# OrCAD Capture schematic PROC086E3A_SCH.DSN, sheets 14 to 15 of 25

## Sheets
14 16. VOUT MUX SELECTION: size C; title: VIN/VOUT MUX SELECTION
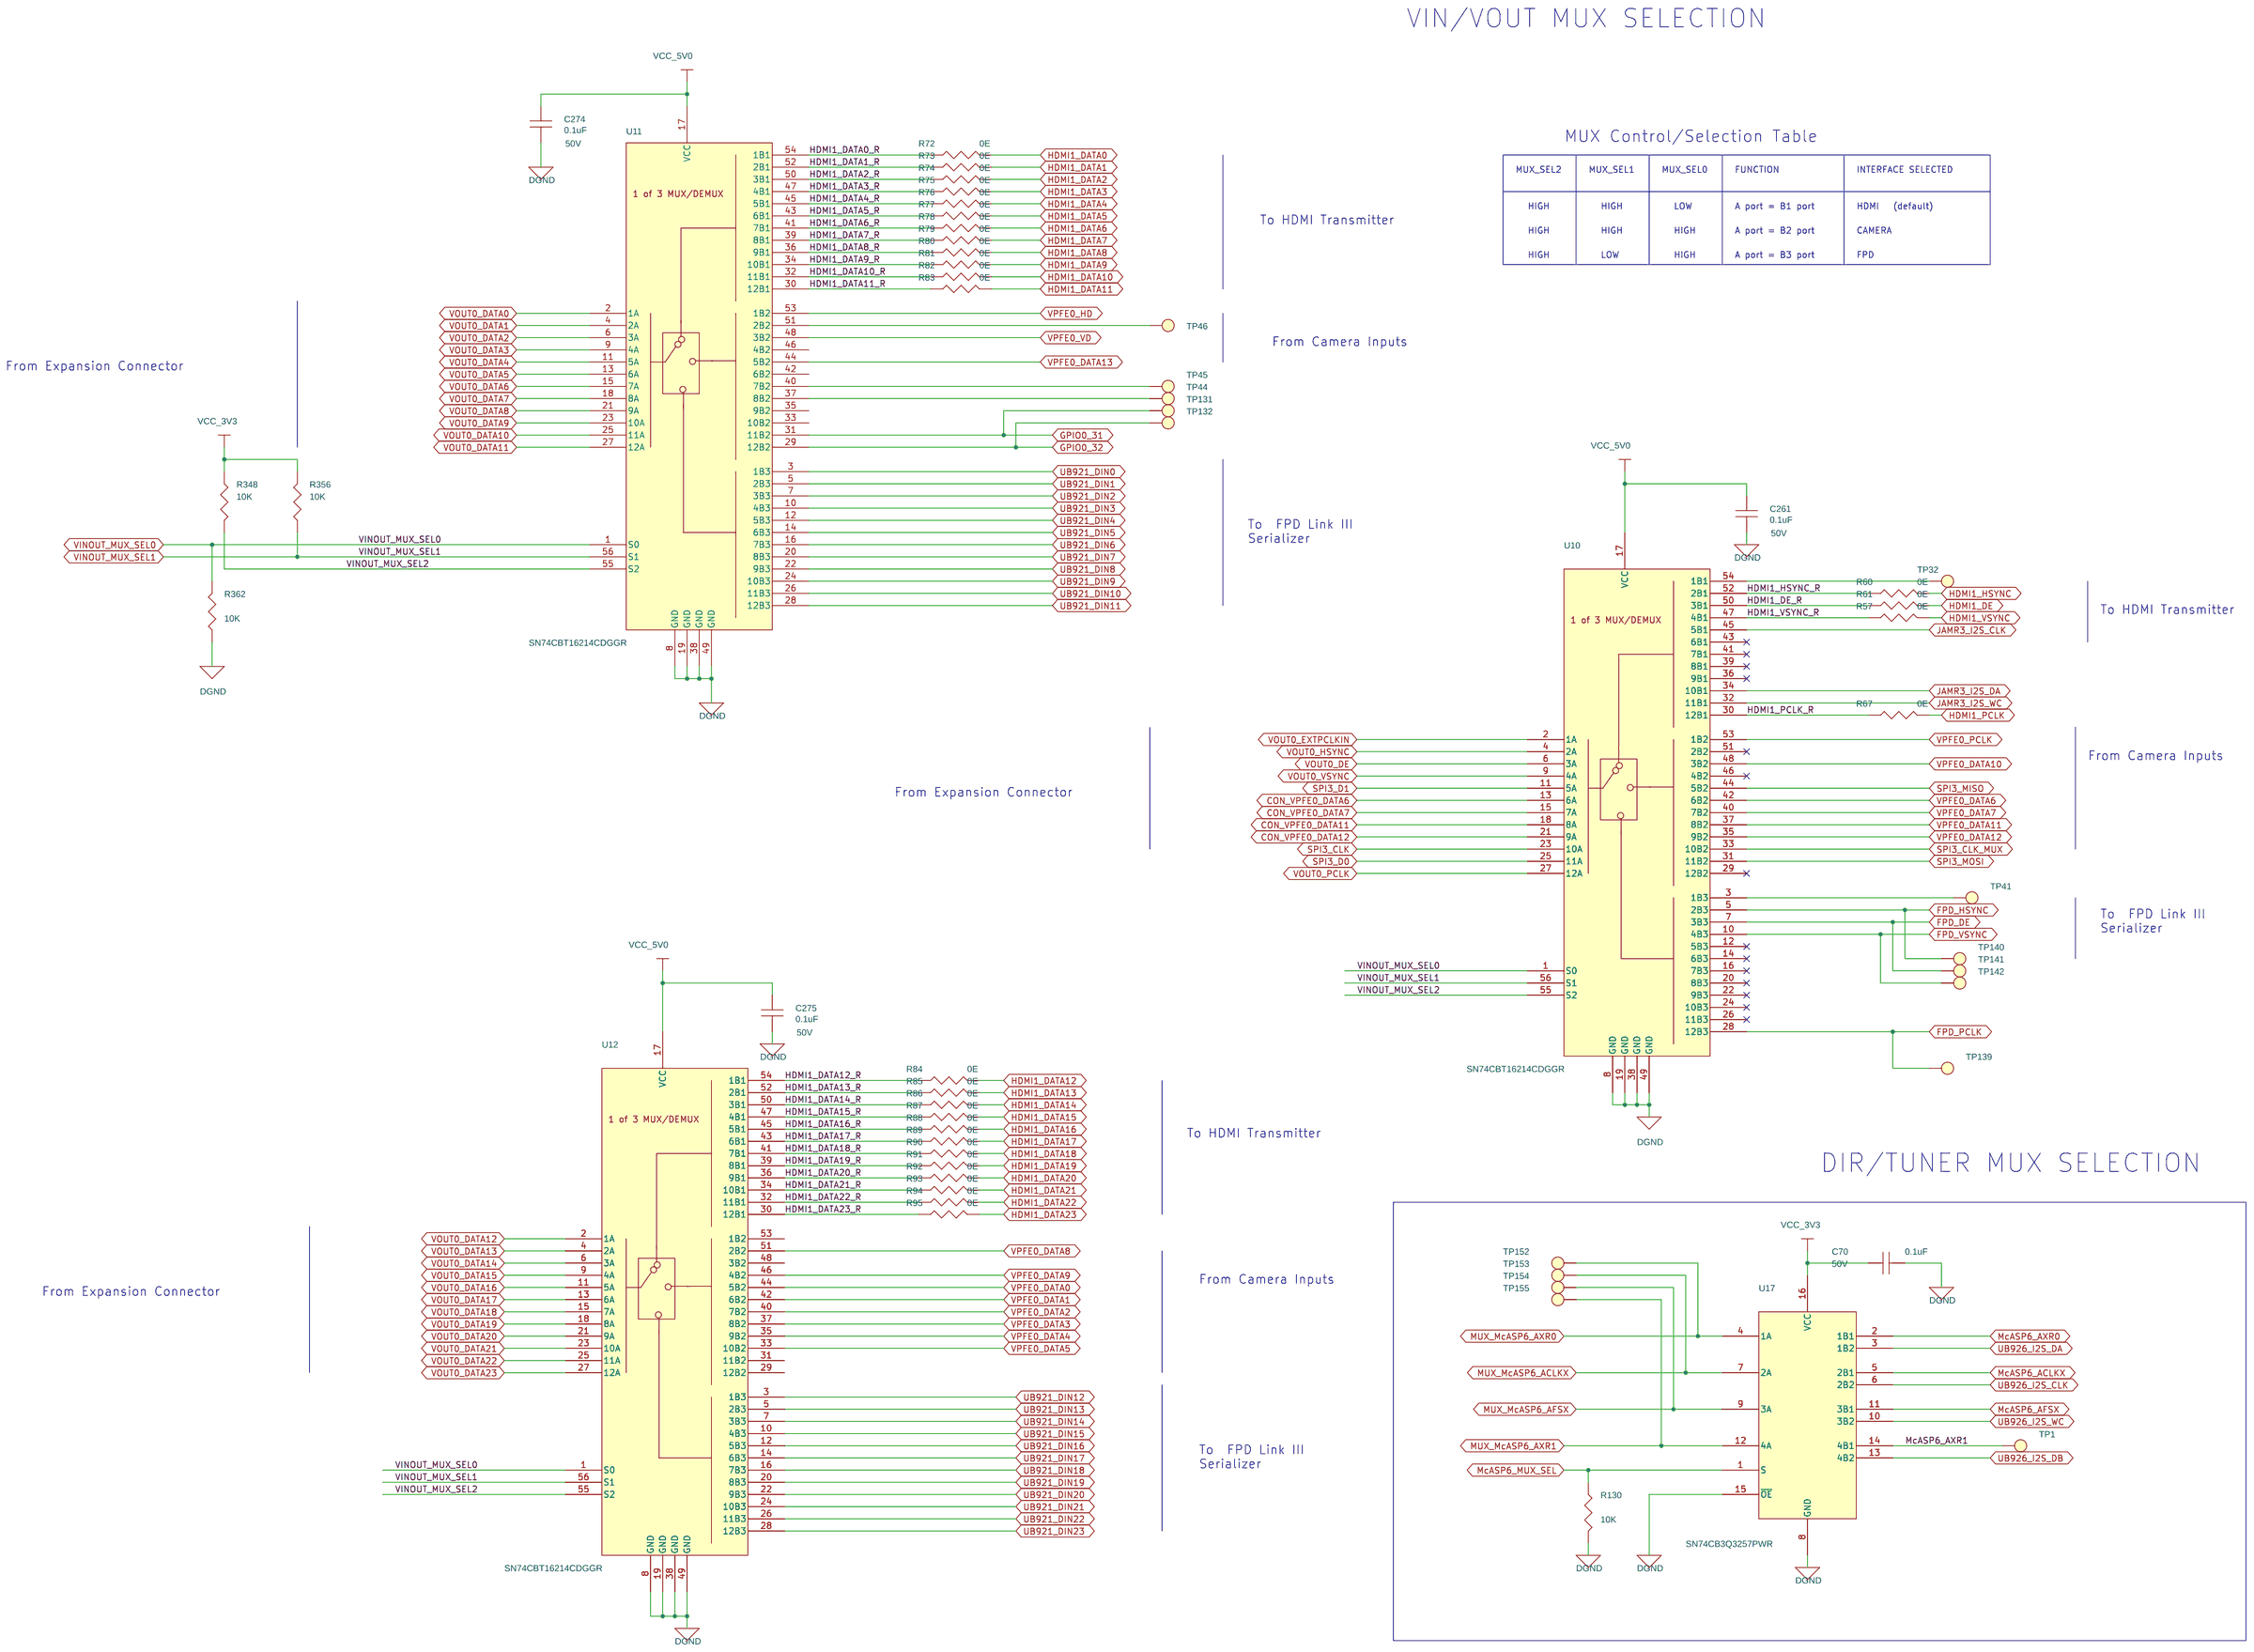
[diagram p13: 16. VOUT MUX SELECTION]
15 17. HDMI BRIDGE: size C; title: HDMI BRIDGE
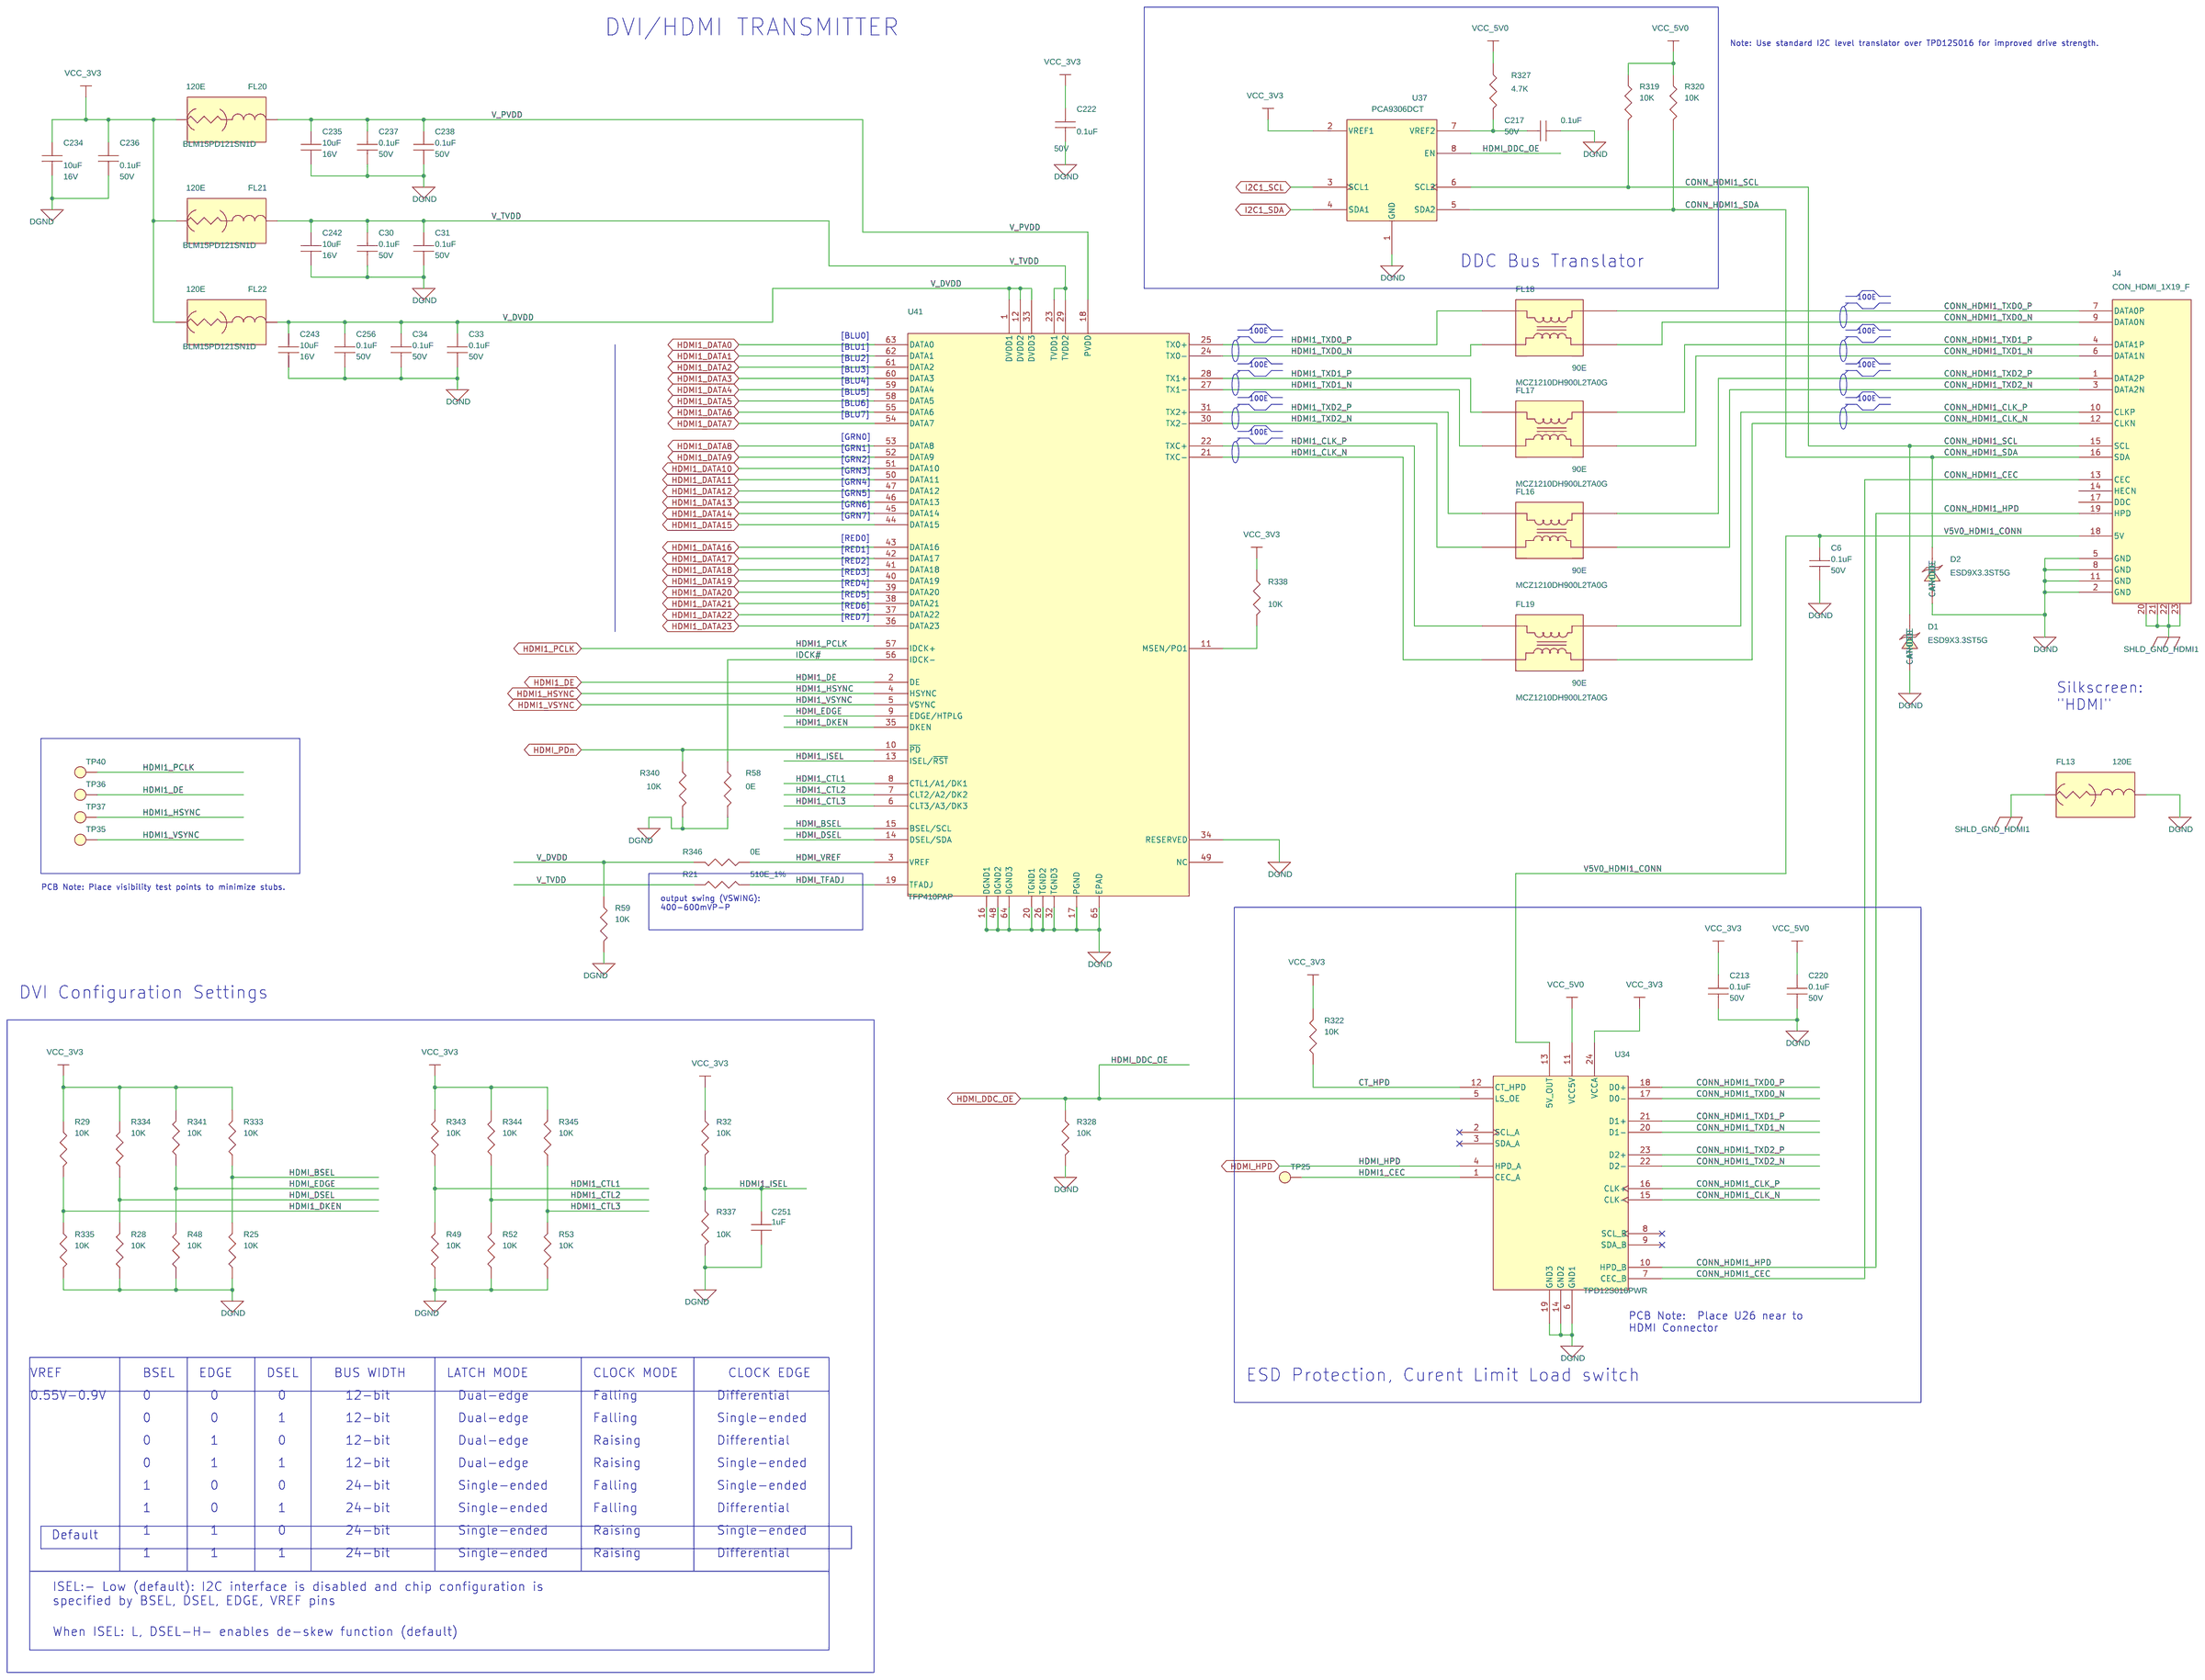
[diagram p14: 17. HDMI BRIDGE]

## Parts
sheet 16. VOUT MUX SELECTION
C70  0.1uF  [CAP0402_0-75]
C261  0.1uF  [CAP0402_0-75]
C274  0.1uF  [CAP0402_0-75]
C275  0.1uF  [CAP0402_0-75]
R57  0E  [RES0402_0-5]
R60  0E  [RES0402_0-5]
R61  0E  [RES0402_0-5]
R67  0E  [RES0402_0-5]
R72  0E  [RES0402_0-5]
R73  0E  [RES0402_0-5]
R74  0E  [RES0402_0-5]
R75  0E  [RES0402_0-5]
R76  0E  [RES0402_0-5]
R77  0E  [RES0402_0-5]
R78  0E  [RES0402_0-5]
R79  0E  [RES0402_0-5]
R80  0E  [RES0402_0-5]
R81  0E  [RES0402_0-5]
R82  0E  [RES0402_0-5]
R83  0E  [RES0402_0-5]
R84  0E  [RES0402_0-5]
R85  0E  [RES0402_0-5]
R86  0E  [RES0402_0-5]
R87  0E  [RES0402_0-5]
R88  0E  [RES0402_0-5]
R89  0E  [RES0402_0-5]
R90  0E  [RES0402_0-5]
R91  0E  [RES0402_0-5]
R92  0E  [RES0402_0-5]
R93  0E  [RES0402_0-5]
R94  0E  [RES0402_0-5]
R95  0E  [RES0402_0-5]
R130  10K  [RES0402_0-5]
R348  10K  [RES0402_0-5]
R356  10K  [RES0402_0-5]
R362  10K  [RES0402_0-5]
TP1  TP40_SMD  [TP40_SMD]
TP32  TP40_SMD  [TP40_SMD]
TP41  TP40_SMD  [TP40_SMD]
TP44  TP40_SMD  [TP40_SMD]
TP45  TP40_SMD  [TP40_SMD]
TP46  TP40_SMD  [TP40_SMD]
TP131  TP20_SMD  [TP20_SMD]
TP132  TP20_SMD  [TP20_SMD]
TP139  TP20_SMD  [TP20_SMD]
TP140  TP20_SMD  [TP20_SMD]
TP141  TP20_SMD  [TP20_SMD]
TP142  TP20_SMD  [TP20_SMD]
TP152  TP20_SMD  [TP20_SMD]
TP153  TP20_SMD  [TP20_SMD]
TP154  TP20_SMD  [TP20_SMD]
TP155  TP20_SMD  [TP20_SMD]
U10  SN74CBT16214CDGGR  [TSSOP56_19-68_560X240_1-2]
U11  SN74CBT16214CDGGR  [TSSOP56_19-68_560X240_1-2]
U12  SN74CBT16214CDGGR  [TSSOP56_19-68_560X240_1-2]
U17  SN74CB3Q3257PWR  [TSSOP16_25-59_205X180]
sheet 17. HDMI BRIDGE
C6  0.1uF  [CAP0402_0-75]
C30  0.1uF  [CAP0402_0-75]
C31  0.1uF  [CAP0402_0-75]
C33  0.1uF  [CAP0402_0-75]
C34  0.1uF  [CAP0402_0-75]
C213  0.1uF  [CAP0402_0-75]
C217  0.1uF  [CAP0402_0-75]
C220  0.1uF  [CAP0402_0-75]
C222  0.1uF  [CAP0402_0-75]
C234  10uF  [CAP0603_1]
C235  10uF  [CAP0603_1]
C236  0.1uF  [CAP0402_0-75]
C237  0.1uF  [CAP0402_0-75]
C238  0.1uF  [CAP0402_0-75]
C242  10uF  [CAP0603_1]
C243  10uF  [CAP0603_1]
C251  1uF  [CAP0402_0-5]
C256  0.1uF  [CAP0402_0-75]
D1  ESD9X3.3ST5G  [DIO_SOD923_0-5]
D2  ESD9X3.3ST5G  [DIO_SOD923_0-5]
FL13  120E  [EMIFIL_BLM15A_0402_0-6]
FL16  90E  [FILT4_MCZ1210DH_60X50_SMD_0-6]
FL17  90E  [FILT4_MCZ1210DH_60X50_SMD_0-6]
FL18  90E  [FILT4_MCZ1210DH_60X50_SMD_0-6]
FL19  90E  [FILT4_MCZ1210DH_60X50_SMD_0-6]
FL20  120E  [EMIFIL_BLM15A_0402_0-6]
FL21  120E  [EMIFIL_BLM15A_0402_0-6]
FL22  120E  [EMIFIL_BLM15A_0402_0-6]
J4  CON_HDMI_1X19_F  [CON_19X1_10029449-001RLF_S_R_S_6-3]
R21  510E_1%  [RES0402_0-5]
R25  10K  [RES0402_0-5]
R28  10K  [RES0402_0-5]
R29  10K  [RES0402_0-5]
R32  10K  [RES0402_0-5]
R48  10K  [RES0402_0-5]
R49  10K  [RES0402_0-5]
R52  10K  [RES0402_0-5]
R53  10K  [RES0402_0-5]
R58  0E  [RES0402_0-5]
R59  10K  [RES0402_0-5]
R319  10K  [RES0402_0-5]
R320  10K  [RES0402_0-5]
R322  10K  [RES0402_0-5]
R327  4.7K  [RES0402_0-5]
R328  10K  [RES0402_0-5]
R333  10K  [RES0402_0-5]
R334  10K  [RES0402_0-5]
R335  10K  [RES0402_0-5]
R337  10K  [RES0402_0-5]
R338  10K  [RES0402_0-5]
R340  10K  [RES0402_0-5]
R341  10K  [RES0402_0-5]
R343  10K  [RES0402_0-5]
R344  10K  [RES0402_0-5]
R345  10K  [RES0402_0-5]
R346  0E  [RES0402_0-5]
TP25  TP40_SMD  [TP40_SMD]
TP35  TP20_SMD  [TP20_SMD]
TP36  TP20_SMD  [TP20_SMD]
TP37  TP20_SMD  [TP20_SMD]
TP40  TP20_SMD  [TP20_SMD]
U34  TPD12S016PWR  [TSSOP24_25-59_315X180_1-2]
U37  PCA9306DCT  [SSOP8_25-59_120X110]
U41  TFP410PAP  [HTQFP64_19-68_400X400_1-2]

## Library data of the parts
C6 C30 C31 C33 C34 C70 C213 C217 C220 C222 C236-C238 C256 C261 C274 C275 = CAP: CAP CERAMIC 0.1uF 50V 10% X7R 0402; Chkd/date: VASANTHA/281216; Crtd /date: CHAITHANYA/051011; Custom_Duty: 15%; Customs_HS_Code: 85322990; Distributor_name: DIGIKEY; Distributor_part_number: 445-173610-1-ND; Footprint Path: Y:\MIS_DATABASE\Library\ALTIUM_TOOL\PCB_FOOTPRINTS\Altium_Footprint_Lib.PcbLib; Height: 0.60MM; Library Path: Y:\MIS_DATABASE\Library\ALTIUM_TOOL\SCHEMATICS_PARTS\MS_DISCRETE_Library.schlib; Mfr_name: TDK CORPORATION; Mfr_part_number: C1005X7R1H104K050BE; Mistral Part No: 120011100014-R; Package: 0402; Part_type: CAPACITORS\CERAMIC; Project: VP-4000-BASE-BOARD; RoHS: RoHS; Temperature: -55°C+125°C; Tolerance: 10%; Voltage: 50V; Wattage: NA; Weight: 0.65mg; Datasheet: Y:\MIS_DATABASE\DATASHEETS\CAPACITORS\TDK_C-SER_FEB19.PDF
R57 R58 R60 R61 R67 R72-R95 R346 = RESISTOR: RES 0E 1/10W JUMPER 0402; Chkd/date: VASANTHA/061216; Crtd /date: NAVEED/201014; Custom_Duty: 15%; Customs_HS_Code: 85332119; Distributor_name: DIGIKEY; Distributor_part_number: P0.0JCT-ND; Footprint Path: Y:\MIS_DATABASE\Library\ALTIUM_TOOL\PCB_FOOTPRINTS\Altium_Footprint_Lib.PcbLib; Height: 0.40MM; IBISSP_MODLES: VALUE REPEATING 2 TIME; Library Path: Y:\MIS_DATABASE\Library\ALTIUM_TOOL\SCHEMATICS_PARTS\MS_DISCRETE_Library.schlib; Mfr_name: PANASONIC-ECG; Mfr_part_number: ERJ-2GE0R00X; Mistral Part No: 110018030052-R; Package: 0402; Part_type: RESISTORS\FIXED; Project: AEGIS POM; RoHS: RoHS; Temperature: -55°C+155°C; Tolerance: NA; Voltage: NA; Wattage: 1/10W; Weight: 0.8mg; Datasheet: Y:\MIS_DATABASE\DATASHEETS\RESISTORS\PAN-ERJSER_NOV17.PDF
R28 R29 R49 R52 R130 R319 R320 R322 R328 R333 R337 R338 R340 R341 R345 R348 R356 R362 = RESISTOR: RES 10K 1/16W 5% 0402; Chkd/date: VASANTHA/061216; Crtd /date: MAZHAR/230805; Custom_Duty: 15%; Customs_HS_Code: 85332119; Distributor_name: DIGIKEY; Distributor_part_number: 311-10KJRCT-ND; Footprint Path: Y:\MIS_DATABASE\Library\ALTIUM_TOOL\PCB_FOOTPRINTS\Altium_Footprint_Lib.PcbLib; Height: 0.40MM; Library Path: Y:\MIS_DATABASE\Library\ALTIUM_TOOL\SCHEMATICS_PARTS\MS_DISCRETE_Library.schlib; Mfr_name: YAGEO AMERICA; Mfr_part_number: RC0402JR-0710KL; Mistral Part No: 110011060021-R; Package: 0402; Part_type: RESISTORS\FIXED; Project: HSE; RoHS: RoHS; Temperature: -55°C+155°C; Tolerance: 5%; Voltage: NA; Wattage: 1/16W; Weight: 0.65mg; Datasheet: Y:\MIS_DATABASE\DATASHEETS\RESISTORS\RCXXXXL-SER_MAR18.PDF
TP1 TP25 TP32 TP41 TP44-TP46 = TESTPOINT: TESTPOINT CIR 40 SMD; Chkd/date: MAZHAR/190505; Crtd /date: MAZHAR/190505; Distributor_name: NA; Distributor_part_number: NA; Footprint Path: Y:\MIS_DATABASE\Library\ALTIUM_TOOL\PCB_FOOTPRINTS\Altium_Footprint_Lib.PcbLib; Height: NA; Library Path: Y:\MIS_DATABASE\Library\ALTIUM_TOOL\SCHEMATICS_PARTS\MS_DISCRETE_Library.schlib; MECHANICAL 3D STEP FILE: NA; Mfr_name: LOCAL; Mistral Part No: 130009030933; Package: SMD; Project: RAINIER-3; RoHS: NA; Temperature: NA; Tolerance: NA; Voltage: NA; Wattage: NA; Weight: NA; Datasheet: NA
TP35-TP37 TP40 TP131 TP132 TP139-TP142 TP152-TP155 = TESTPOINT: TESTPOINT CIR 20 SMD; Chkd/date: SHREESHAIL/171006; Crtd /date: MAZHAR/171006; Custom_Duty: NA; Customs_HS_Code: NA; Distributor_name: NA; Distributor_part_number: NA; Footprint Path: Y:\MIS_DATABASE\Library\ALTIUM_TOOL\PCB_FOOTPRINTS\Altium_Footprint_Lib.PcbLib; Height: NA; Library Path: Y:\MIS_DATABASE\Library\ALTIUM_TOOL\SCHEMATICS_PARTS\MS_DISCRETE_Library.schlib; MECHANICAL 3D STEP FILE: NA; Mfr_name: LOCAL; Mistral Part No: NA; Package: SMD; Project: BT MODULE_CSRBC04; RoHS: NA; Temperature: NA; Tolerance: NA; Voltage: NA; Wattage: NA; Weight: NA; Datasheet: NA
U10-U12 = SN74CBT16214CDGGR_TSSOP56_TI: IC 12BIT 1-OF-3 FET MULTIPLEXER/DEMULTIPLEXER TSSOP56; Chkd/date: VASANTHA/110216; Crtd /date: VASANTHA/110216; Custom_Duty: 15%; Customs_HS_Code: 85423100; Distributor_name: DIGIKEY; Distributor_part_number: 296-19173-1-ND; Footprint Path: Y:\MIS_DATABASE\Library\ALTIUM_TOOL\PCB_FOOTPRINTS\Altium_Footprint_Lib.PcbLib; Height: 1.20MM; Library Path: Y:\MIS_DATABASE\Library\ALTIUM_TOOL\SCHEMATICS_PARTS\MS_COMBINATIONAL_Library.schlib; Library Ref: SN74CBT16214CDGGR_TSSOP56; Mfr_name: TEXAS INSTRUMENTS; Mistral Part No: 141016020009-R; Package: TSSOP56; Part_type: ICS\DIGITAL\COMBINATIONAL; Project: DM368_EVM; RoHS: RoHS; Temperature: -40°C+85°C; Tolerance: NA; Voltage: NA; Wattage: NA; Weight: NA; Datasheet: Y:\MIS_DATABASE\DATASHEETS\ICS\DIGITAL\COMBINATIONAL\SN74CBT16214CD.PDF
U17 = SN74CB3Q3257PWR_TSSOP16: IC 4BIT 1-OF-2 FET MULTIPLEXER/DEMULTIPLEXER TSSOP16; Chkd/date: SUHAS/251010; Crtd /date: USMAN/060109; Custom_Duty: 15%; Customs_HS_Code: 85423100; Distributor_name: DIGIKEY; Distributor_part_number: 296-19138-1-ND; Height: 1.20MM; Mfr_name: TEXAS INSTRUMENTS; Mistral Part No: 141009030117-R; Package: TSSOP16; Part_type: ICS\DIGITAL\COMBINATIONAL; Project: OMAP_EVM; RoHS: Sb/ Br FREE; Temperature: -40°C+85°C; Datasheet: Y:\MIS_DATABASE\DATASHEETS\ICS\DIGITAL\COMBINATIONAL\SN74CB3Q3257.PDF
C234 C235 C242 C243 = CAP: CAP CERAMIC 10uF 16V 20% X6S 0603; Chkd/date: VASANTHA/170117; Crtd /date: VASANTHA/170117; Custom_Duty: 15%; Customs_HS_Code: 85322990; Distributor_name: DIGIKEY; Distributor_part_number: 490-7198-1-ND; Footprint Path: Y:\MIS_DATABASE\Library\ALTIUM_TOOL\PCB_FOOTPRINTS\Altium_Footprint_Lib.PcbLib; Height: 0.90MM; Library Path: Y:\MIS_DATABASE\Library\ALTIUM_TOOL\SCHEMATICS_PARTS\MS_DISCRETE_Library.schlib; Mfr_name: MURATA; Mfr_part_number: GRM188C81C106MA73D; Mistral Part No: 120017010004-R; Package: 0603; Part_type: CAPACITORS\CERAMIC; Project: TRMM_SMART-M_PS; RoHS: RoHS; Temperature: -55°C+105°C; Tolerance: 20%; Voltage: 16V; Wattage: NA; Weight: 6.3mg; Datasheet: Y:\MIS_DATABASE\DATASHEETS\CAPACITORS\MURATA-GXX-SER_NOV17.PDF
C251 = CAP: CAP CERAMIC 1uF 16V 10% X5R 0402; Chkd/date: MANIRAJA/260618; Crtd /date: ALVY/260618; Custom_Duty: 15%; Customs_HS_Code: 85322990; Distributor_name: DIGIKEY; Distributor_part_number: 445-13181-1-ND; Footprint Path: Y:\MIS_DATABASE\Library\ALTIUM_TOOL\PCB_FOOTPRINTS\Altium_Footprint_Lib.PcbLib; Height: 0.33MM; Library Path: Y:\MIS_DATABASE\Library\ALTIUM_TOOL\SCHEMATICS_PARTS\MS_DISCRETE_Library.schlib; Mfr_name: TDK CORPORATION; Mfr_part_number: CGB2A1X5R1C105K033BC; Mistral Part No: 120018060036-R; Package: 0402; Part_type: CAPACITORS\CERAMIC; Project: MYTHIC_PCIE_DB; RoHS: RoHS; Temperature: -55°C+85°C; Tolerance: 10%; Voltage: 16V; Wattage: NA; Weight: 0.65mg; Datasheet: Y:\MIS_DATABASE\DATASHEETS\CAPACITORS\TDK-CG-SER.PDF
D1 D2 = DIODE_TVS: DIODE TVS LOW CAPACITANCE ESD PROTECTION SOD923; Chkd/date: MANIRAJA/120417; Crtd /date: MANIRAJA/120417; Custom_Duty: 15%; Customs_HS_Code: 85412900; Distributor_name: DIGIKEY; Distributor_part_number: ESD9X3.3ST5GOSCT-ND; Footprint Path: Y:\MIS_DATABASE\Library\ALTIUM_TOOL\PCB_FOOTPRINTS\Altium_Footprint_Lib.PcbLib; Height: 0.43MM; Library Path: Y:\MIS_DATABASE\Library\ALTIUM_TOOL\SCHEMATICS_PARTS\MS_DISCRETE_Library.schlib; Mfr_name: ON SEMICONDUCTOR; Mistral Part No: 130017040015-R; Package: SOD923; Part_type: DIODE\TVS; Project: SD820_NANO_SOM; RoHS: RoHS; Temperature: -55°C+150°C; Tolerance: NA; Voltage: 3.3V; Wattage: NA; Weight: NA; Datasheet: Y:\MIS_DATABASE\DATASHEETS\DISCRETES\DIODES\ESD9X.PDF
FL13 FL20-FL22 = EMIFILTER_IND: IND FERRITE BEAD CHIP 120E 1.3A 0402; Chkd/date: VASANTHA/010117; Crtd /date: CHAITHANYA/150312; Custom_Duty: 24%; Customs_HS_Code: 85437099; Distributor_name: DIGIKEY; Distributor_part_number: 490-5203-1-ND; Footprint Path: Y:\MIS_DATABASE\Library\ALTIUM_TOOL\PCB_FOOTPRINTS\Altium_Footprint_Lib.PcbLib; Height: 0.55MM; Library Path: Y:\MIS_DATABASE\Library\ALTIUM_TOOL\SCHEMATICS_PARTS\MS_FILTER_Library.schlib; Mfr_name: MURATA; Mfr_part_number: BLM15PD121SN1D; Mistral Part No: 130012030043-R; Package: 0402; Part_type: FILTER; Project: GEN_3-8; RoHS: RoHS; Temperature: -55°C+125°C; Tolerance: 25%; Voltage: NA; Wattage: NA; Weight: 0.65mg; Datasheet: Y:\MIS_DATABASE\DATASHEETS\DISCRETES\INDUCTORS\BLM15X-SER.PDF
FL16-FL19 = EMIFILTER_ACM: FILTER COMMON MODE 90E 100mA SMD; Chkd/date: MANIRAJA/220818; Crtd /date: ALVY/220818; Custom_Duty: 24%; Customs_HS_Code: 85437099; Distributor_name: DIGIKEY; Distributor_part_number: 445-174550-1-ND; Footprint Path: Y:\MIS_DATABASE\Library\ALTIUM_TOOL\PCB_FOOTPRINTS\Altium_Footprint_Lib.PcbLib; Height: 0.60MM; Library Path: Y:\MIS_DATABASE\Library\ALTIUM_TOOL\SCHEMATICS_PARTS\MS_FILTER_Library.schlib; Mfr_name: TDK CORPORATION; Mfr_part_number: MCZ1210DH900L2TA0G; Mistral Part No: 130018080027-R; Package: SMD; Part_type: FILTER; Project: TI_J7ES_EVM_FUSION2_SER_CAP; RoHS: RoHS; Temperature: -40°C+85°C; Tolerance: 25%; Voltage: NA; Wattage: NA; Weight: 3mg; Datasheet: Y:\MIS_DATABASE\DATASHEETS\ICS\MISC\MCZ1210DH-SER.PDF
J4 = CON_HDMI_19X1_TI: CON HDMI-A TYPE 1X19 0.50MM PITCH FEMALE RT SMD; Chkd/date: VASANTHA/060117; Crtd /date: MUDDU/060510; Custom_Duty: 24%; Customs_HS_Code: 85369090; Distributor_name: DIGIKEY; Distributor_part_number: 609-1010-1-ND; Footprint Path: Y:\MIS_DATABASE\Library\ALTIUM_TOOL\PCB_FOOTPRINTS\Altium_Footprint_Lib.PcbLib; Height: 6.30MM; Library Path: Y:\MIS_DATABASE\Library\ALTIUM_TOOL\SCHEMATICS_PARTS\MS_CONNECTOR_Library.schlib; Library Ref: CON_HDMI_19X1; Mfr_name: FCI; Mfr_part_number: 10029449-001RLF; Mistral Part No: 150010050001-R; Package: SMD; Part_type: CONNECTOR\HDMI; Project: SHIVA; RoHS: RoHS; Temperature: -20°C+85°C; Tolerance: NA; Voltage: NA; Wattage: NA; Weight: 2700mg; Datasheet: Y:\MIS_DATABASE\DATASHEETS\CONNECTORS\10029449-001RLF.PDF
R21 = RESISTOR: RES 510E 1/16W 1% 0402; Chkd/date: MAZHAR/220709; Crtd /date: USMAN/070109; Custom_Duty: 15%; Customs_HS_Code: 85332119; Distributor_name: DIGIKEY; Distributor_part_number: 311-510LRCT-ND; Footprint Path: Y:\MIS_DATABASE\Library\ALTIUM_TOOL\PCB_FOOTPRINTS\Altium_Footprint_Lib.PcbLib; Height: 0.40MM; Library Path: Y:\MIS_DATABASE\Library\ALTIUM_TOOL\SCHEMATICS_PARTS\MS_DISCRETE_Library.schlib; Mfr_name: YAGEO AMERICA; Mfr_part_number: RC0402FR-07510RL; Mistral Part No: 110009030958-R; Package: 0402; Part_type: RESISTORS\FIXED; Project: OMAP_EVM; RoHS: RoHS; Temperature: -55°C+155°C; Tolerance: 1%; Voltage: NA; Wattage: 1/16W; Weight: 0.65mg; Datasheet: Y:\MIS_DATABASE\DATASHEETS\RESISTORS\RCXXXXL-SER_MAR18.PDF
R25 R32 R48 R53 R59 R334 R335 R343 R344 = RESISTOR: RES 10K 1/16W 5% 0402; Assembly_Instruction: DNI; Chkd/date: VASANTHA/061216; Crtd /date: MAZHAR/230805; Custom_Duty: 15%; Customs_HS_Code: 85332119; Distributor_name: DIGIKEY; Distributor_part_number: 311-10KJRCT-ND; Footprint Path: Y:\MIS_DATABASE\Library\ALTIUM_TOOL\PCB_FOOTPRINTS\Altium_Footprint_Lib.PcbLib; Height: 0.40MM; Library Path: Y:\MIS_DATABASE\Library\ALTIUM_TOOL\SCHEMATICS_PARTS\MS_DISCRETE_Library.schlib; Mfr_name: YAGEO AMERICA; Mfr_part_number: RC0402JR-0710KL; Mistral Part No: 110011060021-R; Package: 0402; Part_type: RESISTORS\FIXED; Project: HSE; RoHS: RoHS; Temperature: -55°C+155°C; Tolerance: 5%; Voltage: NA; Wattage: 1/16W; Weight: 0.65mg; Datasheet: Y:\MIS_DATABASE\DATASHEETS\RESISTORS\RCXXXXL-SER_MAR18.PDF
R327 = RESISTOR: RES 4.7K 1/16W 5% 0402; Chkd/date: VASANTHA/281216; Crtd /date: BAVISH/010611; Custom_Duty: 15%; Customs_HS_Code: 85332119; Distributor_name: DIGIKEY; Distributor_part_number: 541-4.7KJCT-ND; Footprint Path: Y:\MIS_DATABASE\Library\ALTIUM_TOOL\PCB_FOOTPRINTS\Altium_Footprint_Lib.PcbLib; Height: 0.40MM; Library Path: Y:\MIS_DATABASE\Library\ALTIUM_TOOL\SCHEMATICS_PARTS\MS_DISCRETE_Library.schlib; Mfr_name: VISHAY; Mfr_part_number: CRCW04024K70JNED; Mistral Part No: 110011060001-R; Package: 0402; Part_type: RESISTORS\FIXED; Project: AM4515_EVM_LCD; RoHS: RoHS; Temperature: -55°C+155°C; Tolerance: 5%; Voltage: NA; Wattage: 1/16W; Weight: 0.65mg; Datasheet: Y:\MIS_DATABASE\DATASHEETS\RESISTORS\CRCW0603.PDF
U34 = TPD12S016PW_TSSOP24: IC HDMI COMPANION CHIP WITH I2C LEVEL SHIFTING,12-CH ESD TSSOP24; Chkd/date: MANIRAJA/110917; Crtd /date: BAVISH/180811; Custom_Duty: 15%; Customs_HS_Code: 85423100; Distributor_name: DIGIKEY; Distributor_part_number: 296-29690-1-ND; Height: 1.20MM; Mfr_name: TEXAS INSTRUMENTS; Mistral Part No: 141011080021-R; Package: TSSOP24; Part_type: ICS\INTERFACE; Project: DM385EVM_BASE-BOARD; RoHS: RoHS; Temperature: -40°C+85°C; Tolerance: NA; Voltage: NA; Wattage: NA; Weight: 212mg; Datasheet: Y:\MIS_DATABASE\DATASHEETS\ICS\INTERFACE\TPD12S016.PDF
U37 = PCA9306DCT_SSOP8: IC VOLTAGE LEVEL TRANSLATORS SSOP8; Chkd/date: MAZHAR/231210; Crtd /date: BAVISH/221210; Custom_Duty: 15%; Customs_HS_Code: 85423100; Distributor_name: DIGIKEY; Distributor_part_number: 296-18509-1-ND; Height: 1.30MM; Mfr_name: TEXAS INSTRUMENTS; Mfr_part_number: PCA9306DCTR; Mistral Part No: 141010120015-R; Package: SSOP8; Part_type: ICS\INTERFACE; Project: CENTAURUS; RoHS: RoHS; Temperature: -40°C+85°C; Tolerance: NA; Voltage: NA; Wattage: NA; Weight: NA; Datasheet: Y:\MIS_DATABASE\DATASHEETS\ICS\INTERFACE\PCA9306DCT.PDF
U41 = TFP410PAP_HTQFP64_TI: IC DIGITAL TRANSMITTER HTQFP64; Chkd/date: MANIRAJA/150917; Crtd /date: USMAN/060109; Custom_Duty: 15%; Customs_HS_Code: 85423100; Distributor_name: DIGIKEY; Distributor_part_number: 296-12666-ND; Footprint Path: Y:\MIS_DATABASE\Library\ALTIUM_TOOL\PCB_FOOTPRINTS\Altium_Footprint_Lib.PcbLib; Height: 1.20MM; Library Path: Y:\MIS_DATABASE\Library\ALTIUM_TOOL\SCHEMATICS_PARTS\MS_COMBINATIONAL_Library.schlib; Library Ref: TFP410PAP_HTQFP64; Mfr_name: TEXAS INSTRUMENTS; Mistral Part No: 141009030307-R; Package: HTQFP64; Part_type: ICS\DIGITAL\PERIPHERAL; Project: OMAP_EVM; RoHS: RoHS; Temperature: 0°C+70°C; Tolerance: NA; Voltage: NA; Wattage: NA; Weight: 258.2mg; Datasheet: Y:\MIS_DATABASE\DATASHEETS\ICS\DIGITAL\PERIPHERAL\TFP410PAP.PDF

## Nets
DGND: C6.2 C30.2 C31.2 C33.2 C34.2 C70.2 C213.2 C217.2 C220.2 C222.2 C234.2 C235.2 C236.2 C237.2 C238.2 C242.2 C243.2 C251.2 C256.2 C261.2 C274.2 C275.2 D1.2(ANODE) D2.2(ANODE) FL13.1 J4.2(GND) J4.5(GND) J4.8(GND) J4.11(GND) R25.2 R28.2 R48.2 R49.2 R52.2 R53.2 R58.2 R59.2 R130.1 R328.2 R335.2 R337.2 R340.1 R362.1 U10.8(GND) U10.19(GND) U10.38(GND) U10.49(GND) U11.8(GND) U11.19(GND) U11.38(GND) U11.49(GND) U12.8(GND) U12.19(GND) U12.38(GND) U12.49(GND) U17.8(GND) U17.15(~{OE}) U34.6(GND1) U34.14(GND2) U34.19(GND3) U37.1(GND) U41.16(DGND1) U41.17(PGND) U41.20(TGND1) U41.26(TGND2) U41.32(TGND3) U41.34(RESERVED) U41.48(DGND2) U41.64(DGND3) U41.65(EPAD) ; also on sheet 5 6 7 8 9 10 11 12 13 16 17 18 19 20 21 22 23 25
V5V0_HDMI1_CONN: C6.1 J4.18(5V) U34.13(5V_OUT)
VCC_3V3: C70.1 C213.1 C222.1 C234.1 C236.1 FL20.2 FL21.2 FL22.2 R29.1 R32.1 R322.2 R333.1 R334.1 R338.2 R341.1 R343.1 R344.1 R345.1 R348.1 R356.2 U17.16(VCC) U34.24(VCCA) U37.2(VREF1) ; also on sheet 5 16 17 18 19 20 21 22 23 25
VCC_5V0: C220.1 C261.1 C274.1 C275.1 R319.1 R320.1 R327.2 U10.17(VCC) U11.17(VCC) U12.17(VCC) U34.11(VCC5V) ; also on sheet 5 6 9 17 22 23
VINOUT_MUX_SEL0: R362.2 U10.1(S0) U11.1(S0) U12.1(S0) ; also on sheet 5
VINOUT_MUX_SEL1: R356.1 U10.56(S1) U11.56(S1) U12.56(S1) ; also on sheet 5
VINOUT_MUX_SEL2: R348.2 U10.55(S2) U11.55(S2) U12.55(S2)
CON_VPFE0_DATA6: U10.13(6A) ; also on sheet 5
CON_VPFE0_DATA7: U10.15(7A) ; also on sheet 5
CON_VPFE0_DATA11: U10.18(8A) ; also on sheet 5
CON_VPFE0_DATA12: U10.21(9A) ; also on sheet 5
CONN_HDMI1_CEC: J4.13(CEC) U34.7(CEC_B)
CONN_HDMI1_CLK_N: FL19.3 J4.12(CLKN) U34.15(CLK-)
CONN_HDMI1_CLK_P: FL19.4 J4.10(CLKP) U34.16(CLK+)
CONN_HDMI1_HPD: J4.19(HPD) U34.10(HPD_B)
CONN_HDMI1_SCL: D1.1(CATHODE) J4.15(SCL) R319.2 U37.6(SCL2)
CONN_HDMI1_SDA: D2.1(CATHODE) J4.16(SDA) R320.2 U37.5(SDA2)
CONN_HDMI1_TXD0_N: FL18.3 J4.9(DATA0N) U34.17(D0-)
CONN_HDMI1_TXD0_P: FL18.4 J4.7(DATA0P) U34.18(D0+)
CONN_HDMI1_TXD1_N: FL17.3 J4.6(DATA1N) U34.20(D1-)
CONN_HDMI1_TXD1_P: FL17.4 J4.4(DATA1P) U34.21(D1+)
CONN_HDMI1_TXD2_N: FL16.3 J4.3(DATA2N) U34.22(D2-)
CONN_HDMI1_TXD2_P: FL16.4 J4.1(DATA2P) U34.23(D2+)
CT_HPD: R322.1 U34.12(CT_HPD)
FPD_DE: TP141.1(TP) U10.7(3B3) ; also on sheet 16
FPD_HSYNC: TP140.1(TP) U10.5(2B3) ; also on sheet 16
FPD_PCLK: TP139.1(TP) U10.28(12B3) ; also on sheet 16
FPD_VSYNC: TP142.1(TP) U10.10(4B3) ; also on sheet 16
GPIO0_31: TP131.1(TP) U11.31(11B2) ; also on sheet 21
GPIO0_32: TP132.1(TP) U11.29(12B2) ; also on sheet 21
HDMI1_CEC: TP25.1(TP) U34.1(CEC_A)
HDMI1_CLK_N: FL19.2 U41.21(TXC-)
HDMI1_CLK_P: FL19.1 U41.22(TXC+)
HDMI1_CTL1: R49.1 R343.2 U41.8(CTL1/A1/DK1)
HDMI1_CTL2: R52.1 R344.2 U41.7(CLT2/A2/DK2)
HDMI1_CTL3: R53.1 R345.2 U41.6(CLT3/A3/DK3)
HDMI1_DATA0: R72.2 U41.63(DATA0)
HDMI1_DATA0_R: R72.1 U11.54(1B1)
HDMI1_DATA1: R73.2 U41.62(DATA1)
HDMI1_DATA1_R: R73.1 U11.52(2B1)
HDMI1_DATA2: R74.2 U41.61(DATA2)
HDMI1_DATA2_R: R74.1 U11.50(3B1)
HDMI1_DATA3: R75.2 U41.60(DATA3)
HDMI1_DATA3_R: R75.1 U11.47(4B1)
HDMI1_DATA4: R76.2 U41.59(DATA4)
HDMI1_DATA4_R: R76.1 U11.45(5B1)
HDMI1_DATA5: R77.2 U41.58(DATA5)
HDMI1_DATA5_R: R77.1 U11.43(6B1)
HDMI1_DATA6: R78.2 U41.55(DATA6)
HDMI1_DATA6_R: R78.1 U11.41(7B1)
HDMI1_DATA7: R79.2 U41.54(DATA7)
HDMI1_DATA7_R: R79.1 U11.39(8B1)
HDMI1_DATA8: R80.2 U41.53(DATA8)
HDMI1_DATA8_R: R80.1 U11.36(9B1)
HDMI1_DATA9: R81.2 U41.52(DATA9)
HDMI1_DATA9_R: R81.1 U11.34(10B1)
HDMI1_DATA10: R82.2 U41.51(DATA10)
HDMI1_DATA10_R: R82.1 U11.32(11B1)
HDMI1_DATA11: R83.2 U41.50(DATA11)
HDMI1_DATA11_R: R83.1 U11.30(12B1)
HDMI1_DATA12: R84.2 U41.47(DATA12)
HDMI1_DATA12_R: R84.1 U12.54(1B1)
HDMI1_DATA13: R85.2 U41.46(DATA13)
HDMI1_DATA13_R: R85.1 U12.52(2B1)
HDMI1_DATA14: R86.2 U41.45(DATA14)
HDMI1_DATA14_R: R86.1 U12.50(3B1)
HDMI1_DATA15: R87.2 U41.44(DATA15)
HDMI1_DATA15_R: R87.1 U12.47(4B1)
HDMI1_DATA16: R88.2 U41.43(DATA16)
HDMI1_DATA16_R: R88.1 U12.45(5B1)
HDMI1_DATA17: R89.2 U41.42(DATA17)
HDMI1_DATA17_R: R89.1 U12.43(6B1)
HDMI1_DATA18: R90.2 U41.41(DATA18)
HDMI1_DATA18_R: R90.1 U12.41(7B1)
HDMI1_DATA19: R91.2 U41.40(DATA19)
HDMI1_DATA19_R: R91.1 U12.39(8B1)
HDMI1_DATA20: R92.2 U41.39(DATA20)
HDMI1_DATA20_R: R92.1 U12.36(9B1)
HDMI1_DATA21: R93.2 U41.38(DATA21)
HDMI1_DATA21_R: R93.1 U12.34(10B1)
HDMI1_DATA22: R94.2 U41.37(DATA22)
HDMI1_DATA22_R: R94.1 U12.32(11B1)
HDMI1_DATA23: R95.2 U41.36(DATA23)
HDMI1_DATA23_R: R95.1 U12.30(12B1)
HDMI1_DE: R61.2 TP36.1(TP) U41.2(DE)
HDMI1_DE_R: R61.1 U10.50(3B1)
HDMI1_DKEN: R29.2 R335.1 U41.35(DKEN)
HDMI1_HSYNC: R60.2 TP37.1(TP) U41.4(HSYNC)
HDMI1_HSYNC_R: R60.1 U10.52(2B1)
HDMI1_ISEL: C251.1 R32.2 R337.1 U41.13(ISEL/~{RST})
HDMI1_PCLK: R67.2 TP40.1(TP) U41.57(IDCK+)
HDMI1_PCLK_R: R67.1 U10.30(12B1)
HDMI1_TXD0_N: FL18.2 U41.24(TX0-)
HDMI1_TXD0_P: FL18.1 U41.25(TX0+)
HDMI1_TXD1_N: FL17.2 U41.27(TX1-)
HDMI1_TXD1_P: FL17.1 U41.28(TX1+)
HDMI1_TXD2_N: FL16.2 U41.30(TX2-)
HDMI1_TXD2_P: FL16.1 U41.31(TX2+)
HDMI1_VSYNC: R57.2 TP35.1(TP) U41.5(VSYNC)
HDMI1_VSYNC_R: R57.1 U10.47(4B1)
HDMI_BSEL: R25.1 R333.2 U41.15(BSEL/SCL)
HDMI_DDC_OE: R328.1 U34.5(LS_OE) U37.8(EN) ; also on sheet 5
HDMI_DSEL: R28.1 R334.2 U41.14(DSEL/SDA)
HDMI_EDGE: R48.1 R341.2 U41.9(EDGE/HTPLG)
HDMI_HPD: U34.4(HPD_A) ; also on sheet 5
HDMI_PDn: R340.2 U41.10(~{PD}) ; also on sheet 5
HDMI_TFADJ: R21.2 U41.19(TFADJ)
HDMI_VREF: R346.1 U41.3(VREF)
I2C1_SCL: U37.3(SCL1) ; also on sheet 5 16
I2C1_SDA: U37.4(SDA1) ; also on sheet 5 16
IDCK#: R58.1 U41.56(IDCK-)
JAMR3_I2S_CLK: U10.45(5B1) ; also on sheet 18
JAMR3_I2S_DA: U10.34(10B1) ; also on sheet 18
JAMR3_I2S_WC: U10.32(11B1) ; also on sheet 18
McASP6_ACLKX: U17.5(2B1) ; also on sheet 19
McASP6_AFSX: U17.11(3B1) ; also on sheet 19
McASP6_AXR0: U17.2(1B1) ; also on sheet 19
McASP6_AXR1: TP1.1(TP) U17.14(4B1)
McASP6_MUX_SEL: R130.2 U17.1(S) ; also on sheet 5
MUX_McASP6_ACLKX: TP153.1(TP) U17.7(2A) ; also on sheet 5
MUX_McASP6_AFSX: TP154.1(TP) U17.9(3A) ; also on sheet 5
MUX_McASP6_AXR0: TP152.1(TP) U17.4(1A) ; also on sheet 5
MUX_McASP6_AXR1: TP155.1(TP) U17.12(4A) ; also on sheet 5
SHLD_GND_HDMI1: FL13.2 J4.20 J4.21 J4.22 J4.23
SPI3_CLK: U10.23(10A) ; also on sheet 5
SPI3_CLK_MUX: U10.33(10B2) ; also on sheet 21
SPI3_D0: U10.25(11A) ; also on sheet 5
SPI3_D1: U10.11(5A) ; also on sheet 5
SPI3_MISO: U10.44(5B2) ; also on sheet 21
SPI3_MOSI: U10.31(11B2) ; also on sheet 21
UB921_DIN0: U11.3(1B3) ; also on sheet 16
UB921_DIN1: U11.5(2B3) ; also on sheet 16
UB921_DIN2: U11.7(3B3) ; also on sheet 16
UB921_DIN3: U11.10(4B3) ; also on sheet 16
UB921_DIN4: U11.12(5B3) ; also on sheet 16
UB921_DIN5: U11.14(6B3) ; also on sheet 16
UB921_DIN6: U11.16(7B3) ; also on sheet 16
UB921_DIN7: U11.20(8B3) ; also on sheet 16
UB921_DIN8: U11.22(9B3) ; also on sheet 16
UB921_DIN9: U11.24(10B3) ; also on sheet 16
UB921_DIN10: U11.26(11B3) ; also on sheet 16
UB921_DIN11: U11.28(12B3) ; also on sheet 16
UB921_DIN12: U12.3(1B3) ; also on sheet 16
UB921_DIN13: U12.5(2B3) ; also on sheet 16
UB921_DIN14: U12.7(3B3) ; also on sheet 16
UB921_DIN15: U12.10(4B3) ; also on sheet 16
UB921_DIN16: U12.12(5B3) ; also on sheet 16
UB921_DIN17: U12.14(6B3) ; also on sheet 16
UB921_DIN18: U12.16(7B3) ; also on sheet 16
UB921_DIN19: U12.20(8B3) ; also on sheet 16
UB921_DIN20: U12.22(9B3) ; also on sheet 16
UB921_DIN21: U12.24(10B3) ; also on sheet 16
UB921_DIN22: U12.26(11B3) ; also on sheet 16
UB921_DIN23: U12.28(12B3) ; also on sheet 16
UB926_I2S_CLK: U17.6(2B2) ; also on sheet 20
UB926_I2S_DA: U17.3(1B2) ; also on sheet 20
UB926_I2S_DB: U17.13(4B2) ; also on sheet 20
UB926_I2S_WC: U17.10(3B2) ; also on sheet 20
V_DVDD: C33.1 C34.1 C243.1 C256.1 FL22.1 R59.1 R346.2 U41.1(DVDD1) U41.12(DVDD2) U41.33(DVDD3)
V_PVDD: C235.1 C237.1 C238.1 FL20.1 U41.18(PVDD)
V_TVDD: C30.1 C31.1 C242.1 FL21.1 R21.1 U41.23(TVDD1) U41.29(TVDD2)
VOUT0_DATA0: U11.2(1A) ; also on sheet 5
VOUT0_DATA1: U11.4(2A) ; also on sheet 5
VOUT0_DATA2: U11.6(3A) ; also on sheet 5
VOUT0_DATA3: U11.9(4A) ; also on sheet 5
VOUT0_DATA4: U11.11(5A) ; also on sheet 5
VOUT0_DATA5: U11.13(6A) ; also on sheet 5
VOUT0_DATA6: U11.15(7A) ; also on sheet 5
VOUT0_DATA7: U11.18(8A) ; also on sheet 5
VOUT0_DATA8: U11.21(9A) ; also on sheet 5
VOUT0_DATA9: U11.23(10A) ; also on sheet 5
VOUT0_DATA10: U11.25(11A) ; also on sheet 5
VOUT0_DATA11: U11.27(12A) ; also on sheet 5
VOUT0_DATA12: U12.2(1A) ; also on sheet 5
VOUT0_DATA13: U12.4(2A) ; also on sheet 5
VOUT0_DATA14: U12.6(3A) ; also on sheet 5
VOUT0_DATA15: U12.9(4A) ; also on sheet 5
VOUT0_DATA16: U12.11(5A) ; also on sheet 5
VOUT0_DATA17: U12.13(6A) ; also on sheet 5
VOUT0_DATA18: U12.15(7A) ; also on sheet 5
VOUT0_DATA19: U12.18(8A) ; also on sheet 5
VOUT0_DATA20: U12.21(9A) ; also on sheet 5
VOUT0_DATA21: U12.23(10A) ; also on sheet 5
VOUT0_DATA22: U12.25(11A) ; also on sheet 5
VOUT0_DATA23: U12.27(12A) ; also on sheet 5
VOUT0_DE: U10.6(3A) ; also on sheet 5
VOUT0_EXTPCLKIN: U10.2(1A) ; also on sheet 5
VOUT0_HSYNC: U10.4(2A) ; also on sheet 5
VOUT0_PCLK: U10.27(12A) ; also on sheet 5
VOUT0_VSYNC: U10.9(4A) ; also on sheet 5
VPFE0_DATA0: U12.44(5B2) ; also on sheet 21
VPFE0_DATA1: U12.42(6B2) ; also on sheet 21
VPFE0_DATA2: U12.40(7B2) ; also on sheet 21
VPFE0_DATA3: U12.37(8B2) ; also on sheet 21
VPFE0_DATA4: U12.35(9B2) ; also on sheet 21
VPFE0_DATA5: U12.33(10B2) ; also on sheet 21
VPFE0_DATA6: U10.42(6B2) ; also on sheet 21
VPFE0_DATA7: U10.40(7B2) ; also on sheet 21
VPFE0_DATA8: U12.51(2B2) ; also on sheet 21
VPFE0_DATA9: U12.46(4B2) ; also on sheet 21
VPFE0_DATA10: U10.48(3B2) ; also on sheet 21
VPFE0_DATA11: U10.37(8B2) ; also on sheet 21
VPFE0_DATA12: U10.35(9B2) ; also on sheet 21
VPFE0_DATA13: U11.44(5B2) ; also on sheet 21
VPFE0_HD: U11.53(1B2) ; also on sheet 21
VPFE0_PCLK: U10.53(1B2) ; also on sheet 21
VPFE0_VD: U11.48(3B2) ; also on sheet 21
N23276319: R338.1 U41.11(MSEN/PO1)
N24673543: TP44.1(TP) U11.37(8B2)
N24673545: TP45.1(TP) U11.40(7B2)
N24673547: TP46.1(TP) U11.51(2B2)
N24676160: TP41.1(TP) U10.3(1B3)
N24676162: TP32.1(TP) U10.54(1B1)
N24788879: C217.1 R327.1 U37.7(VREF2)

Not connected (* = marked no-connect by the designer): J4 14(HECN) 17(DDC); U10 12(5B3)* 14(6B3)* 16(7B3)* 20(8B3)* 22(9B3)* 24(10B3)* 26(11B3)* 29(12B2)* 36(9B1)* 39(8B1)* 41(7B1)* 43(6B1)* 46(4B2)* 51(2B2)*; U11 33(10B2) 35(9B2) 42(6B2) 46(4B2); U12 29(12B2) 31(11B2) 48(3B2) 53(1B2); U34 2(SCL_A)* 3(SDA_A)* 8(SCL_B)* 9(SDA_B)*; U41 49(NC)

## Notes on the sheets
sheet 14
- VIN/VOUT MUX SELECTION
- MUX Control/Selection Table
- MUX_SEL2
- MUX_SEL1
- MUX_SEL0
- FUNCTION
- INTERFACE SELECTED
- To HDMI Transmitter
- HIGH
- HIGH
- LOW
- A port = B1 port
- HDMI
- (default)
- HIGH
- HIGH
- HIGH
- A port = B2 port
- CAMERA
- HIGH
- LOW
- HIGH
- A port = B3 port
- FPD
- From Camera Inputs
- From Expansion Connector
- To  FPD Link III
  Serializer
- To HDMI Transmitter
- From Camera Inputs
- From Expansion Connector
- To  FPD Link III
  Serializer
- To HDMI Transmitter
- DIR/TUNER MUX SELECTION
- From Camera Inputs
- From Expansion Connector
- To  FPD Link III
  Serializer
sheet 15
- DVI/HDMI TRANSMITTER
- Note: Use standard I2C level translator over TPD12S016 for improved drive strength.
- DDC Bus Translator
- 100E
- 100E
- 100E
- [BLU0]
- [BLU1]
- [BLU2]
- [BLU3]
- 100E
- 100E
- [BLU4]
- [BLU5]
- 100E
- 100E
- [BLU6]
- [BLU7]
- [GRN0]
- 100E
- [GRN1]
- [GRN2]
- [GRN3]
- [GRN4]
- [GRN5]
- [GRN6]
- [GRN7]
- [RED0]
- [RED1]
- [RED2]
- [RED3]
- [RED4]
- [RED5]
- [RED6]
- [RED7]
- Silkscreen:
  "HDMI"
- PCB Note: Place visibility test points to minimize stubs.
- output swing (VSWING):
  400-600mVP-P
- DVI Configuration Settings
- PCB Note:  Place U26 near to
  HDMI Connector
- VREF
- BSEL
- EDGE
- DSEL
- BUS WIDTH
- LATCH MODE
- CLOCK MODE
- CLOCK EDGE
- ESD Protection, Curent Limit Load switch
- 0.55V-0.9V
- 0
- 0
- 0
- 12-bit
- Dual-edge
- Falling
- Differential
- 0
- 0
- 1
- 12-bit
- Dual-edge
- Falling
- Single-ended
- 0
- 1
- 0
- 12-bit
- Dual-edge
- Raising
- Differential
- 0
- 1
- 1
- 12-bit
- Dual-edge
- Raising
- Single-ended
- 1
- 0
- 0
- 24-bit
- Single-ended
- Falling
- Single-ended
- 1
- 0
- 1
- 24-bit
- Single-ended
- Falling
- Differential
- 1
- 1
- 0
- 24-bit
- Single-ended
- Raising
- Single-ended
- Default
- 1
- 1
- 1
- 24-bit
- Single-ended
- Raising
- Differential
- ISEL:- Low (default): I2C interface is disabled and chip configuration is
  specified by BSEL, DSEL, EDGE, VREF pins
- When ISEL: L, DSEL-H- enables de-skew function (default)
